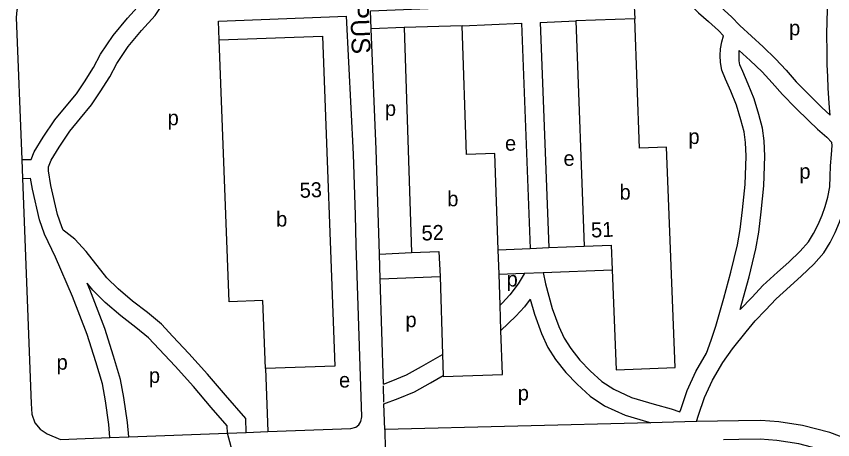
# Model space of a CAD drawing. Extents: x 158358 to 160383, y 379531 to 380764.
# Drawn here: x 159910 to 160127.9, y 379779.7 to 379892.6 of the extents above; entities that cross this region are included whole.
import ezdxf

# ---------------------------------------------------------------- set-up
doc = ezdxf.new("R2010")
doc.units = 0
for name, color, linetype in [('BLT_Basislijn', 7, 'Continuous'), ('BLT_Bebouwing', 7, 'Continuous'), ('BLT_Centroide', 7, 'Continuous'), ('BLT_Huisnummer', 7, 'Continuous'), ('BLT_Straatnaam', 7, 'Continuous'), ('BLT_Vlakafsluiter', 7, 'Continuous')]:
    doc.layers.add(name, color=color, linetype=linetype)

msp = doc.modelspace()

# ---------------------------------------------------------------- linework, layer by layer
at = {"layer": 'BLT_Basislijn'}
for p, q in [((160028.96, 379890.09), (160044.8, 379890.74)), ((160044.8, 379890.74), (160047.15, 379830.72)), ((160049.8, 379890.95), (160059.3, 379891.34)), ((160049.8, 379890.95), (160052.15, 379830.93)), ((160013.49, 379889.57), (160004.76, 379889.27)), ((159911.48, 379854.38), (159914.01, 379854.42)), ((159911.67, 379849.38), (159913.85, 379849.41)), ((160006.9, 379829.14), (160015.52, 379829.65)), ((160038.62, 379830.36), (160047.15, 379830.72)), ((160047.15, 379830.72), (160052.15, 379830.93)), ((160052.15, 379830.93), (160061.6, 379831.34)), ((160007.1, 379822.61), (160023.09, 379823.23)), ((160038.84, 379823.83), (160045.55, 379824.08)), ((160045.55, 379824.08), (160050.61, 379824.28)), ((160050.61, 379824.28), (160069.06, 379824.98)), ((159976.5, 379798.67), (159977.13, 379781.89)), ((159971.36, 379781.67), (159971.24, 379785.36)), ((160008.35, 379782.42), (160008.46, 379777.08))]:
    msp.add_line(p, q, dxfattribs=at)
for points in [[(159914.01, 379854.42), (159914.81, 379856.5), (159917.23, 379860.39), (159920.32, 379864.96), (159923.31, 379868.63), (159926.1, 379871.96), (159928.21, 379875.14), (159930.66, 379878.93), (159932.49, 379882.52), (159935.84, 379887.51), (159939.68, 379892.11), (159943.14, 379895.91), (159948.61, 379904.3), (159953.14, 379910.9), (159956.92, 379917.5), (159960.38, 379922), (159963.53, 379925.68)], [(159922.57, 379835.62), (159922.15, 379836.47), (159921.03, 379839.73), (159919.26, 379847.46), (159918.59, 379851.38), (159918.61, 379852.46), (159919.3, 379854.26), (159921.42, 379857.67), (159924.33, 379861.97), (159927.16, 379865.44), (159930.12, 379868.96), (159932.39, 379872.41), (159935, 379876.43), (159936.81, 379879.98), (159939.85, 379884.51), (159943.45, 379888.82), (159947.11, 379892.84), (159952.77, 379901.52), (159957.38, 379908.24), (159961.09, 379914.72), (159964.27, 379918.85), (159967.1, 379922.16), (159971.26, 379926.33)], [(160127.17, 379866.21), (160126.99, 379868.21), (160126.87, 379870.76), (160126.67, 379873.46), (160126.56, 379876.53), (160126.42, 379879.63), (160126.4, 379882.85), (160126.31, 379888.02), (160126.49, 379894.33), (160126.67, 379899.36), (160126.94, 379904.28), (160127.04, 379906.56)], [(159915.72, 379904.23), (159915.72, 379900.36), (159915.58, 379899.27), (159914.98, 379898.31), (159914.11, 379897.68), (159912.3, 379896.77), (159911.3, 379896.08), (159910.61, 379895.34), (159910.14, 379894.25), (159910.03, 379892.31), (159911.48, 379854.38)], [(160081.74, 379903.74), (160083.29, 379902.35), (160085.96, 379899.66), (160088.91, 379896.67), (160092.06, 379893.52), (160094.76, 379891.23), (160097.37, 379888.83), (160098.77, 379887.41)], [(160004.57, 379894.09), (160074.83, 379896.98), (160075.04, 379891.94)], [(160096.81, 379896.04), (160098.06, 379894.98), (160100.85, 379892.43), (160103.09, 379890.14), (160106.17, 379887.26), (160109.28, 379884.48), (160112.65, 379881.25), (160115.42, 379878.23), (160118.11, 379875.16), (160121.5, 379871.7), (160124.95, 379868.32), (160127.17, 379866.21)], [(159964.16, 379886.29), (159963.98, 379891.29), (159998.14, 379892.58)], [(160000.51, 379839.58), (160000, 379855.88), (159998.14, 379892.58)], [(160004.76, 379889.27), (160004.57, 379894.09)], [(160006.9, 379829.14), (160006.03, 379857.1), (160004.76, 379889.27)], [(160094.21, 379802.75), (160095.49, 379806.26), (160096.67, 379810.02), (160098.84, 379817.46), (160100.7, 379824.36), (160102.46, 379831.66), (160103.19, 379835.79), (160103.8, 379841.01), (160104.51, 379847.73), (160104.77, 379855.26), (160104.6, 379858.94), (160104.23, 379861.8), (160103.39, 379865.03), (160102.19, 379868.92), (160100.69, 379872.59), (160099.26, 379875.87), (160098.25, 379878.25), (160097.9, 379880.31), (160097.88, 379882.14), (160097.91, 379883.89), (160098.31, 379885.8), (160098.77, 379887.41)], [(160103.17, 379814.43), (160103.66, 379816.11), (160105.55, 379823.12), (160107.35, 379830.63), (160108.14, 379835.06), (160108.77, 379840.46), (160109.5, 379847.38), (160109.77, 379855.29), (160109.58, 379859.37), (160109.15, 379862.75), (160108.2, 379866.39), (160106.91, 379870.61), (160105.29, 379874.53), (160103.86, 379877.84), (160103.09, 379879.66), (160102.9, 379880.76), (160102.88, 379882.14), (160102.9, 379883.34), (160102.92, 379883.45)], [(160102.92, 379883.45), (160105.88, 379880.81), (160109.07, 379877.75), (160111.7, 379874.89), (160114.45, 379871.76), (160117.97, 379868.17), (160121.48, 379864.72), (160123.81, 379862.51), (160126.31, 379860.35), (160127.64, 379858.91)], [(160103.17, 379814.43), (160106.35, 379817.71), (160109.26, 379820.86), (160113.18, 379824.36), (160116.15, 379827.06), (160119.24, 379829.95), (160121.43, 379832.5), (160122.79, 379834.72), (160124, 379837.08), (160125.06, 379839.55), (160125.91, 379841.87), (160126.59, 379844.35), (160127.08, 379847.12), (160127.18, 379849.87), (160127.3, 379852.77), (160127.54, 379855.77), (160127.71, 379858.13), (160127.64, 379858.91)], [(159911.48, 379854.38), (159911.67, 379849.38)], [(160091.55, 379784.54), (160092.08, 379786.28), (160093.67, 379790.98), (160095.8, 379795.61), (160098.58, 379800.32), (160101.11, 379803.92), (160104.79, 379808.48), (160107.17, 379811.38), (160109.98, 379814.27), (160112.77, 379817.29), (160116.53, 379820.65), (160119.53, 379823.39), (160122.86, 379826.48), (160125.49, 379829.55), (160127.16, 379832.27), (160128.53, 379834.95), (160129.71, 379837.7), (160130.68, 379840.34), (160131.48, 379843.25), (160132.06, 379846.59), (160132.18, 379849.68), (160132.29, 379852.47), (160132.44, 379854.28)], [(159911.67, 379849.38), (159913.95, 379789.38), (159914.16, 379786.5), (159914.98, 379784.25), (159916.41, 379782.49), (159918.28, 379781.28), (159921.79, 379779.77)], [(159935.01, 379780.28), (159934.75, 379783.8), (159933.83, 379790.11), (159932.99, 379794.58), (159931.21, 379800.49), (159928.89, 379807.73), (159925.03, 379817.89), (159920.51, 379828.42), (159917.53, 379834.55), (159916.22, 379838.36), (159914.35, 379846.48), (159913.85, 379849.41)], [(160000.76, 379831.58), (160000.51, 379839.58)], [(159971.24, 379785.36), (159965.83, 379791.55), (159961.06, 379797.23), (159956.05, 379802.74), (159951.77, 379807.24), (159948.79, 379810.51), (159945.04, 379813.6), (159941.02, 379816.61), (159937.18, 379819.93), (159934.2, 379822.88), (159928.64, 379829.87), (159925.6, 379833.18), (159923.26, 379835.02), (159922.57, 379835.62)], [(160002.2, 379785.85), (160000.76, 379831.58)], [(160007.1, 379822.61), (160006.9, 379829.14)], [(160045.57, 379823.98), (160043.98, 379821.31), (160041.75, 379818.36), (160039.7, 379816.13), (160039.12, 379815.57)], [(160045.55, 379824.08), (160045.57, 379823.98)], [(160050.61, 379824.28), (160051.24, 379821.26), (160053.04, 379814.68), (160054.78, 379809.93), (160056.23, 379806.75), (160058.01, 379804), (160060.43, 379800.91), (160063.15, 379798.1), (160066.23, 379795.28), (160069.44, 379793.15), (160074.23, 379790.96), (160080.21, 379789.18), (160084.77, 379787.91), (160087.1, 379787.11)], [(159940.01, 379780.47), (159939.72, 379784.35), (159938.76, 379790.93), (159937.85, 379795.77), (159935.98, 379801.98), (159933.61, 379809.38), (159929.67, 379819.77), (159928.94, 379821.46)], [(159966.3, 379783.41), (159962.03, 379788.3), (159957.29, 379793.94), (159952.39, 379799.33), (159948.11, 379803.83), (159945.33, 379806.88), (159941.95, 379809.67), (159937.88, 379812.71), (159933.78, 379816.26), (159930.47, 379819.54), (159928.94, 379821.46)], [(160007.97, 379794.57), (160007.1, 379822.61)], [(160047.16, 379817.22), (160045.6, 379815.15), (160043.28, 379812.63), (160039.35, 379808.84)], [(160047.16, 379817.22), (160048.27, 379813.16), (160050.15, 379808.03), (160051.84, 379804.34), (160053.93, 379801.1), (160056.65, 379797.62), (160059.66, 379794.51), (160063.14, 379791.33), (160067, 379788.77), (160072.47, 379786.27), (160078.83, 379784.37), (160079.32, 379784.24)], [(160007.97, 379794.57), (160010.07, 379795.36), (160014.11, 379796.98), (160018.12, 379799.24), (160023.76, 379802.47)], [(160087.1, 379787.11), (160087.32, 379787.81), (160089.02, 379792.84), (160091.36, 379797.93), (160094.21, 379802.75)], [(160008.14, 379789.29), (160011.88, 379790.7), (160016.28, 379792.46), (160020.59, 379794.89), (160023.94, 379796.81)], [(160008.12, 379789.73), (160007.99, 379794.08)], [(160008.35, 379782.42), (160008.14, 379789.29)], [(159977.13, 379781.89), (159999.32, 379782.73), (160000.65, 379783.05), (160001.4, 379783.69), (160001.99, 379784.57), (160002.2, 379785.85)], [(160079.32, 379784.24), (160008.35, 379782.42)], [(160091.55, 379784.54), (160088.43, 379784.47), (160079.32, 379784.24)], [(160158.32, 379765.7), (160154.65, 379767.66), (160147.55, 379771.74), (160141.03, 379775.48), (160134.12, 379779), (160127.13, 379781.64), (160119.83, 379783.53), (160113.49, 379784.5), (160108.69, 379784.83), (160102.78, 379784.79), (160091.55, 379784.54)], [(159940.01, 379780.47), (159966.37, 379781.47)], [(159966.37, 379781.47), (159966.3, 379783.41)], [(159966.37, 379781.47), (159971.36, 379781.67)], [(159971.36, 379781.67), (159977.13, 379781.89)], [(159921.79, 379779.77), (159935.01, 379780.28)], [(159935.01, 379780.28), (159940.01, 379780.47)], [(160154.91, 379761.85), (160152.23, 379763.29), (160145.06, 379767.41), (160138.65, 379771.08), (160132.09, 379774.42), (160125.61, 379776.87), (160118.82, 379778.63), (160112.94, 379779.53), (160108.54, 379779.83), (160102.86, 379779.79), (160098.74, 379779.7)]]:
    msp.add_lwpolyline(points, dxfattribs=at)
at = {"layer": 'BLT_Bebouwing'}
for points in [[(160075.04, 379891.94), (160059.3, 379891.34)], [(160059.3, 379891.34), (160061.6, 379831.34)], [(160069.06, 379824.98), (160070.08, 379798.36), (160085.81, 379798.96), (160083.56, 379857.72), (160076.36, 379857.44), (160075.04, 379891.94)], [(160028.96, 379890.09), (160013.49, 379889.57)], [(160013.49, 379889.57), (160015.52, 379829.65)], [(160038.62, 379830.36), (160037.75, 379855.98), (160030.12, 379855.72), (160028.96, 379890.09)], [(159964.16, 379886.29), (159991.73, 379887.33), (159994.99, 379799.35), (159976.5, 379798.67)], [(159976.5, 379798.67), (159975.82, 379816.85), (159966.84, 379816.5), (159964.16, 379886.29)], [(160061.6, 379831.34), (160068.8, 379831.61), (160069.06, 379824.98)], [(160015.52, 379829.65), (160022.82, 379829.9), (160023.09, 379823.23)], [(160038.84, 379823.83), (160038.62, 379830.36)], [(160023.09, 379823.23), (160023.76, 379802.47)], [(160039.12, 379815.57), (160038.84, 379823.83)], [(160039.35, 379808.84), (160039.12, 379815.57)], [(160023.94, 379796.81), (160023.95, 379796.6), (160039.75, 379797.14), (160039.35, 379808.84)], [(160023.76, 379802.47), (160023.94, 379796.81)]]:
    msp.add_lwpolyline(points, dxfattribs=at)
at = {"layer": 'BLT_Vlakafsluiter'}
msp.add_line((159967.95, 379775.53), (159966.37, 379781.47), dxfattribs=at)

# ---------------------------------------------------------------- texts
at = {"layer": 'BLT_Centroide'}
for s, p in [('p', (160116.24, 379887.51)), ('p', (160008.39, 379866.04)), ('p', (159950.41, 379863.54)), ('p', (160089.38, 379858.55)), ('e', (160040.44, 379856.76)), ('e', (160056.04, 379852.73)), ('p', (160118.99, 379849.27)), ('b', (160071, 379843.72)), ('b', (160025.03, 379841.95)), ('b', (159979.36, 379836.54)), ('p', (160040.86, 379820.56)), ('p', (160013.87, 379809.71)), ('p', (159920.78, 379798.38)), ('p', (159945.41, 379794.86)), ('e', (159996.14, 379793.63)), ('p', (160043.84, 379790.18))]:
    msp.add_text(s, height=4, dxfattribs=at).set_placement(p)
at = {"layer": 'BLT_Huisnummer'}
for s, p in [('53', (159985.71, 379844.18)), ('52', (160018.23, 379832.79)), ('51', (160063.46, 379833.61))]:
    msp.add_text(s, height=4, rotation=2.1868, dxfattribs=at).set_placement(p)
at = {"layer": 'BLT_Straatnaam'}
msp.add_text('HIGH TECH CAMPUS', height=5, rotation=272.1866, dxfattribs=at).set_placement((159997.02, 379949.64))

doc.saveas('drawing.dxf')
